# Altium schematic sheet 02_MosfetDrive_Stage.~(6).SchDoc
size A4; SheetNumber: 2; SheetTotal: 2
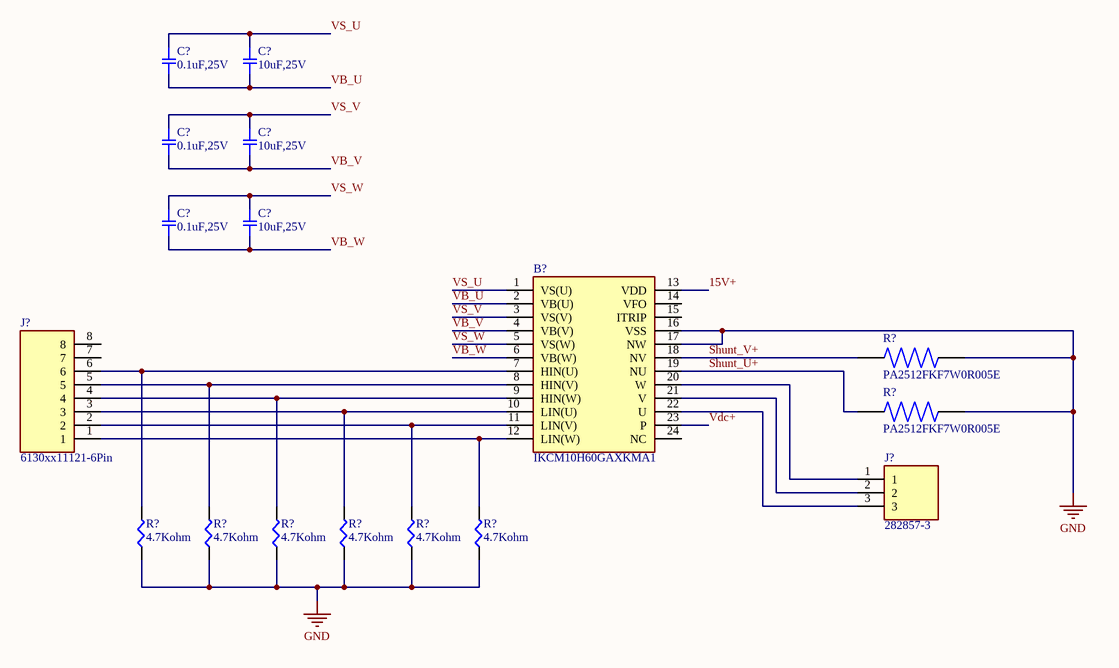
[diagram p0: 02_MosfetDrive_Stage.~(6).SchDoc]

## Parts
(Parts that share a designator on the sheet are numbered #1, #2 ... from top to bottom, then left to right.)
B?  IKCM10H60GAXKMA1  [997_IKCM10H60GAXKMA1]
C?#1  0.1uF,25V  [001_SMD-1206]
C?#2  10uF,25V  [001_SMD-1206]
C?#3  0.1uF,25V  [001_SMD-1206]
C?#4  10uF,25V  [001_SMD-1206]
C?#5  0.1uF,25V  [001_SMD-1206]
C?#6  10uF,25V  [001_SMD-1206]
J?#1  6130xx11121-6Pin  [200_HDRV6W64P0X254_1X6_1524X254X869P]
J?#2  282857-3  [201_TE_282857-3]
R?#1  PA2512FKF7W0R005E  [097_PA2512FKF7W0R005E]
R?#2  PA2512FKF7W0R005E  [097_PA2512FKF7W0R005E]
R?#3  4.7Kohm  [001_SMD-1206]
R?#4  4.7Kohm  [001_SMD-1206]
R?#5  4.7Kohm  [001_SMD-1206]
R?#6  4.7Kohm  [001_SMD-1206]
R?#7  4.7Kohm  [001_SMD-1206]
R?#8  4.7Kohm  [001_SMD-1206]

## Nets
GND: B?.16(VSS) B?.17(NW) R?#1.2 R?#2.2 R?#3.1 R?#4.1 R?#5.1 R?#6.1 R?#7.1 R?#8.1
15V+: B?.13(VDD)
Shunt_U+: B?.19(NU) R?#2.1
Shunt_V+: B?.18(NV) R?#1.1
VB_U: B?.2(VB(U)) C?#1.2 C?#2.2
VB_V: B?.4(VB(V)) C?#3.2 C?#4.2
VB_W: B?.6(VB(W)) C?#5.2 C?#6.2
Vdc+: B?.23(P)
VS_U: B?.1(VS(U)) C?#1.1 C?#2.1
VS_V: B?.3(VS(V)) C?#3.1 C?#4.1
VS_W: B?.5(VS(W)) C?#5.1 C?#6.1
NetB?_7: B?.7(HIN(U)) J?#1.6 R?#3.2
NetB?_8: B?.8(HIN(V)) J?#1.5 R?#4.2
NetB?_9: B?.9(HIN(W)) J?#1.4 R?#5.2
NetB?_10: B?.10(LIN(U)) J?#1.3 R?#6.2
NetB?_11: B?.11(LIN(V)) J?#1.2 R?#7.2
NetB?_12: B?.12(LIN(W)) J?#1.1 R?#8.2
NetB?_20: B?.20(W) J?#2.1
NetB?_21: B?.21(V) J?#2.2
NetB?_22: B?.22(U) J?#2.3

Not connected (* = marked no-connect by the designer): B? 14(VFO) 15(ITRIP) 24(NC); J?#1 7 8

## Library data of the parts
B? = IKCM10H60GAXKMA1: Intelligent Power Module 3-Ph 600V 10A; Manufacturer_Name: Infineon; Geometry.Height: 5.6mm
C?#1-C?#6 = C_1206_Template: CAP CER 1206; Part Number: GC321AD72E103KX01D; Manufacturer: Murata Electronics North America; Factory Stock: 0; Unit Price (USD): 0.3; Minimum Quantity: 1; Value: 10000pF; Tolerance: ±10%; Voltage: 250V; Temperature Coefficient: X7T
J?#1 = 6130xx11121-6Pin: 2.54MM PIN HEADER; Manufacturer_Name: Wurth Elektronik; Geometry.Height: 8.69mm
J?#2 = 282857-3: 3 Position Wire to Board Terminal Block Horizontal with Board 0.200 (5.08mm) Through Hole; MF: TE Connectivity
R?#1 R?#2 = PA2512FKF7W0R005E: 5 mΩ, 2 W, ±1% current-sense shunt resistor, 2512 (6332 metric) SMD package, low-resistance metal-element construction.; MF: Bourns; MP: CRF2512-FZ-R005ELF
R?#3-R?#8 = R_1206_Template: RES SMD 1206; Part Number: ERJ-8BQF1R0V; Manufacturer: Panasonic Electronic Components; Factory Stock: 0; Unit Price (USD): 0.05778; @ qty: 1500; Minimum Quantity: 1; Value: 1; Tolerance: ±1%; Power (Watts): 0.5W, 1/2W; Temperature Coefficient: ±200ppm/°C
